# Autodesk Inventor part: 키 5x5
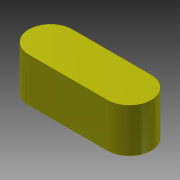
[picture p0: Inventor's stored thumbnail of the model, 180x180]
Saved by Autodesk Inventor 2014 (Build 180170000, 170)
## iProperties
Created: 2016-04
Part Number: 키 5x5
Document SubType Name: Modeling
Designer: mdu
Density: 7.86 g/cm^3
Mass: 2.47598 g
Surface Area: 2.77413 cm^2
Volume: 0.31501 cm^3
Material: 강철, 연강
Appearance: 노란색
Author: mdu
Revision Number: 1
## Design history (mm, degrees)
sketch "스케치1"
  geometry: L1 (-4.5, -2.5)-(4.5, -2.5); L2 (4.5, 2.5)-(-4.5, 2.5); A1 r 2.5 centre (4.5, 0) between (4.5, -2.5) and (4.5, 2.5); A2 r 2.5 centre (-4.5, 0) between (-4.5, 2.5) and (-4.5, -2.5); 2 further points
  constraints: 4 end point, 4 point on circle, 4 tangent, 2 centre point, 1 horizontal, 1 horizontal alignment, 1 midpoint, 1 parallel, 1 vertical alignment
  dimensions: "d0" = 5 distance between parallel lines of L1 L2; "d1" = 14 dimension on A1 A2
extrude "돌출1" new body sketch "스케치1" stored distance "d2" = 5; taper "d3" = 0 deg
chamfer "모따기1" distance "d4" = 0.5; stored, may be unused: second distance "d5" = 2, angle "d6" = 45 deg
node "솔리드1"
other parameters: "d0" = 5
